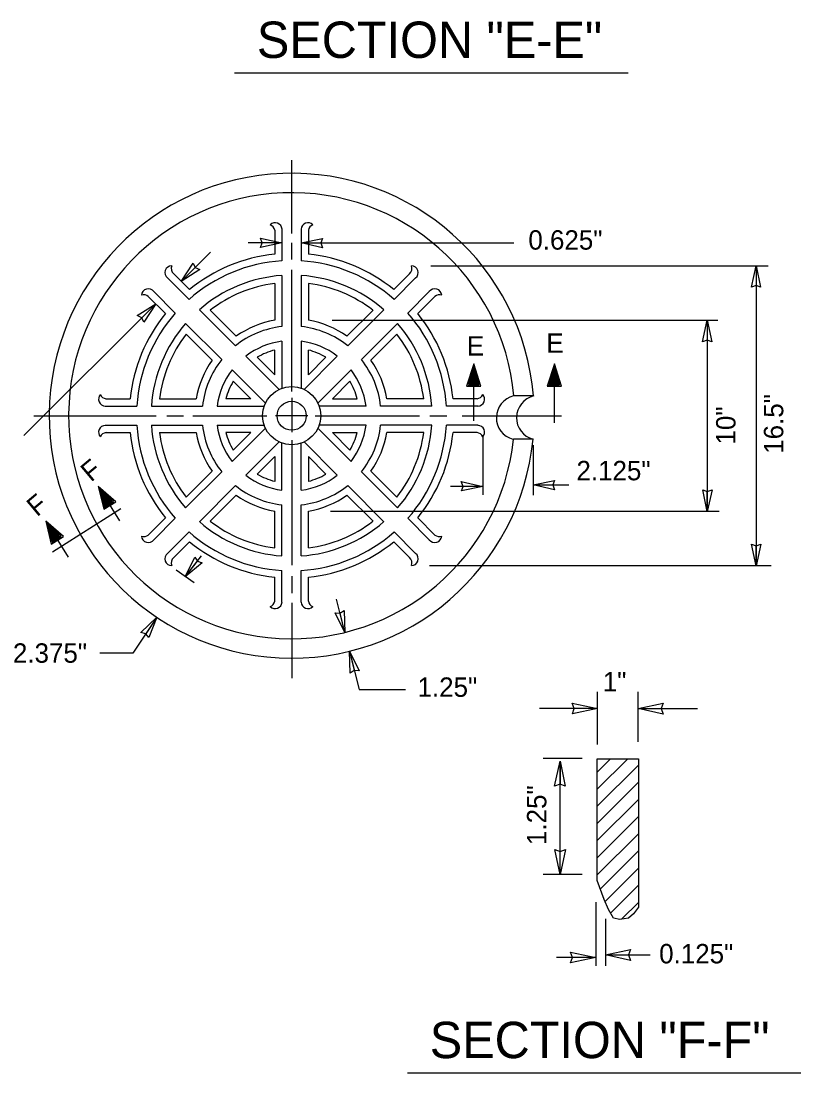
# Model space of a CAD drawing. Extents: x 19188 to 19495, y 20866 to 21061.
# Drawn here: x 19443.2 to 19476.89, y 20917.28 to 20962.72 of the extents above; entities that cross this region are included whole.
import ezdxf

# ---------------------------------------------------------------- set-up
doc = ezdxf.new("R2010")
doc.units = 0
doc.layers.add('G-ANNO-NOTE', color=7, linetype='Continuous')

msp = doc.modelspace()

# ---------------------------------------------------------------- linework, layer by layer
at = {"layer": 'G-ANNO-NOTE'}
for p, q in [((19452.424, 20960.486), (19469.42, 20960.486)), ((19454.471, 20953.729), (19454.471, 20952.36)), ((19455.299, 20953.729), (19455.299, 20952.36)), ((19454.157, 20953.681), (19454.157, 20952.649)), ((19455.613, 20953.681), (19455.613, 20952.649)), ((19454.471, 20953.135), (19453.007, 20953.135)), ((19454.471, 20953.135), (19453.618, 20953.135)), ((19455.299, 20953.135), (19464.487, 20953.135)), ((19455.299, 20953.135), (19456.152, 20953.135)), ((19450.122, 20951.476), (19451.382, 20952.736)), ((19450.122, 20951.476), (19450.725, 20952.079)), ((19460.905, 20952.151), (19475.47, 20952.151)), ((19474.952, 20952.151), (19474.952, 20939.195)), ((19474.952, 20952.151), (19474.952, 20951.298)), ((19450.456, 20950.697), (19449.529, 20951.624)), ((19449.797, 20951.8), (19450.474, 20951.124)), ((19454.471, 20951.731), (19454.471, 20949.523)), ((19455.299, 20951.731), (19455.299, 20949.523)), ((19459.973, 20951.8), (19459.296, 20951.124)), ((19459.314, 20950.697), (19460.241, 20951.624)), ((19448.937, 20951.031), (19449.863, 20950.105)), ((19454.157, 20951.384), (19454.157, 20949.795)), ((19455.613, 20951.384), (19455.613, 20949.795)), ((19460.833, 20951.031), (19459.907, 20950.105)), ((19448.696, 20950.828), (19449.437, 20950.087)), ((19461.074, 20950.828), (19460.333, 20950.087)), ((19449.015, 20950.508), (19443.319, 20944.812)), ((19449.015, 20950.508), (19448.412, 20949.905)), ((19450.901, 20950.252), (19452.462, 20948.691)), ((19451.368, 20950.229), (19452.492, 20949.105)), ((19458.402, 20950.229), (19457.278, 20949.105)), ((19458.869, 20950.252), (19457.308, 20948.691)), ((19450.308, 20949.66), (19451.869, 20948.098)), ((19456.633, 20949.795), (19473.295, 20949.795)), ((19459.461, 20949.66), (19457.9, 20948.098)), ((19472.843, 20949.795), (19472.843, 20941.539)), ((19472.843, 20949.795), (19472.843, 20948.942)), ((19450.331, 20949.192), (19451.455, 20948.069)), ((19459.438, 20949.192), (19458.315, 20948.069)), ((19454.471, 20948.89), (19454.471, 20946.858)), ((19455.299, 20948.89), (19455.299, 20946.858)), ((19454.157, 20947.44), (19454.157, 20948.51)), ((19455.613, 20947.44), (19455.613, 20948.51)), ((19452.909, 20948.243), (19454.347, 20946.806)), ((19454.157, 20947.44), (19453.401, 20948.197)), ((19456.86, 20948.243), (19455.424, 20946.806)), ((19455.613, 20947.44), (19456.37, 20948.197)), ((19462.76, 20945.446), (19462.76, 20947.908)), ((19466.238, 20945.363), (19466.238, 20947.908)), ((19452.317, 20947.651), (19453.757, 20946.211)), ((19457.453, 20947.651), (19456.013, 20946.211)), ((19453.12, 20946.404), (19452.364, 20947.16)), ((19456.65, 20946.404), (19457.407, 20947.16)), ((19462.507, 20946.979), (19462.971, 20946.979)), ((19465.984, 20946.979), (19466.449, 20946.979)), ((19465.328, 20946.527), (19464.487, 20946.527)), ((19446.829, 20946.089), (19448.2, 20946.089)), ((19446.869, 20946.404), (19447.911, 20946.404)), ((19448.83, 20946.089), (19451.037, 20946.089)), ((19449.176, 20946.404), (19450.765, 20946.404)), ((19451.67, 20946.089), (19453.701, 20946.089)), ((19453.12, 20946.404), (19452.05, 20946.404)), ((19454.89, 20946.441), (19454.89, 20944.959)), ((19458.1, 20946.089), (19456.069, 20946.089)), ((19456.65, 20946.404), (19457.719, 20946.404)), ((19460.94, 20946.089), (19458.733, 20946.089)), ((19460.594, 20946.404), (19459.005, 20946.404)), ((19462.941, 20946.089), (19461.57, 20946.089)), ((19462.901, 20946.404), (19461.859, 20946.404)), ((19455.586, 20945.671), (19454.191, 20945.671)), ((19446.829, 20945.258), (19448.2, 20945.258)), ((19448.83, 20945.258), (19451.037, 20945.258)), ((19451.67, 20945.258), (19453.701, 20945.258)), ((19452.317, 20943.696), (19453.757, 20945.137)), ((19457.453, 20943.696), (19456.013, 20945.137)), ((19458.1, 20945.258), (19456.069, 20945.258)), ((19460.94, 20945.258), (19458.733, 20945.258)), ((19462.941, 20945.258), (19461.57, 20945.258)), ((19446.869, 20944.944), (19447.911, 20944.944)), ((19449.176, 20944.944), (19450.765, 20944.944)), ((19453.12, 20944.944), (19452.05, 20944.944)), ((19453.12, 20944.944), (19452.364, 20944.187)), ((19456.65, 20944.944), (19457.407, 20944.187)), ((19456.65, 20944.944), (19457.719, 20944.944)), ((19460.594, 20944.944), (19459.005, 20944.944)), ((19462.901, 20944.944), (19461.859, 20944.944)), ((19463.143, 20944.759), (19463.143, 20942.26)), ((19465.314, 20944.656), (19464.472, 20944.656)), ((19452.909, 20943.104), (19454.347, 20944.541)), ((19454.471, 20942.457), (19454.471, 20944.49)), ((19455.299, 20942.457), (19455.299, 20944.49)), ((19456.86, 20943.104), (19455.424, 20944.541)), ((19465.317, 20944.407), (19465.317, 20942.245)), ((19454.157, 20943.907), (19453.401, 20943.151)), ((19454.157, 20943.907), (19454.157, 20942.837)), ((19455.613, 20943.907), (19456.37, 20943.151)), ((19455.613, 20943.907), (19455.613, 20942.837)), ((19450.331, 20942.155), (19451.455, 20943.279)), ((19459.438, 20942.155), (19458.315, 20943.279)), ((19450.308, 20941.688), (19451.869, 20943.249)), ((19459.461, 20941.688), (19457.9, 20943.249)), ((19446.534, 20942.62), (19447.452, 20941.13)), ((19450.901, 20941.095), (19452.462, 20942.656)), ((19458.869, 20941.095), (19457.308, 20942.656)), ((19463.143, 20942.62), (19461.746, 20942.62)), ((19463.143, 20942.62), (19462.291, 20942.62)), ((19465.317, 20942.68), (19466.86, 20942.68)), ((19465.317, 20942.68), (19466.17, 20942.68)), ((19472.843, 20941.539), (19472.843, 20942.392)), ((19446.806, 20941.696), (19447.201, 20941.94)), ((19451.368, 20941.118), (19452.492, 20942.242)), ((19458.402, 20941.118), (19457.278, 20942.242)), ((19444.552, 20939.787), (19447.505, 20941.659)), ((19454.157, 20939.963), (19454.157, 20941.552)), ((19454.471, 20939.617), (19454.471, 20941.824)), ((19455.299, 20939.617), (19455.299, 20941.824)), ((19455.613, 20939.963), (19455.613, 20941.552)), ((19456.568, 20941.552), (19473.36, 20941.552)), ((19444.268, 20941.118), (19445.229, 20939.558)), ((19448.696, 20940.52), (19449.437, 20941.261)), ((19448.937, 20940.316), (19449.863, 20941.243)), ((19460.833, 20940.316), (19459.907, 20941.243)), ((19461.074, 20940.52), (19460.333, 20941.261)), ((19450.456, 20940.65), (19449.529, 20939.723)), ((19459.314, 20940.65), (19460.241, 20939.723)), ((19444.54, 20940.194), (19444.935, 20940.437)), ((19449.797, 20939.546), (19450.474, 20940.224)), ((19459.973, 20939.546), (19459.296, 20940.224)), ((19474.952, 20939.195), (19474.952, 20940.049)), ((19450.289, 20938.715), (19451, 20939.616)), ((19450.289, 20938.715), (19450.817, 20939.384)), ((19460.84, 20939.196), (19475.599, 20939.196)), ((19449.9, 20939.015), (19450.677, 20938.475)), ((19454.471, 20937.618), (19454.471, 20938.987)), ((19455.299, 20937.618), (19455.299, 20938.987)), ((19454.157, 20937.666), (19454.157, 20938.698)), ((19455.613, 20937.666), (19455.613, 20938.698)), ((19457.179, 20936.311), (19456.827, 20937.754)), ((19449.065, 20936.967), (19448.023, 20935.411)), ((19449.065, 20936.967), (19448.59, 20936.258)), ((19457.179, 20936.311), (19456.977, 20937.14)), ((19448.023, 20935.411), (19446.599, 20935.411)), ((19457.391, 20935.501), (19457.798, 20933.848)), ((19457.391, 20935.501), (19457.595, 20934.673)), ((19457.798, 20933.848), (19459.804, 20933.848)), ((19468.093, 20931.47), (19468.093, 20933.742)), ((19469.853, 20931.59), (19469.853, 20933.742)), ((19468.093, 20933.025), (19465.6, 20933.025)), ((19468.093, 20933.025), (19467.098, 20933.025)), ((19469.853, 20933.025), (19472.42, 20933.025)), ((19469.853, 20933.025), (19470.848, 20933.025)), ((19467.433, 20930.873), (19465.747, 20930.873)), ((19466.48, 20925.852), (19466.48, 20930.753)), ((19466.48, 20930.753), (19466.48, 20929.759)), ((19468.091, 20930.857), (19469.869, 20930.857)), ((19468.091, 20925.598), (19468.091, 20930.857)), ((19468.091, 20929.541), (19469.408, 20930.857)), ((19468.091, 20930.281), (19468.667, 20930.857)), ((19468.091, 20928.8), (19469.869, 20930.578)), ((19469.869, 20930.857), (19469.869, 20924.445)), ((19468.091, 20928.059), (19469.869, 20929.837)), ((19468.091, 20927.319), (19469.869, 20929.097)), ((19468.091, 20926.578), (19469.869, 20928.356)), ((19468.091, 20925.838), (19469.869, 20927.616)), ((19466.48, 20925.852), (19466.48, 20926.847)), ((19468.227, 20925.233), (19469.869, 20926.875)), ((19468.429, 20924.694), (19469.869, 20926.134)), ((19467.433, 20925.852), (19465.747, 20925.852)), ((19468.65, 20924.175), (19469.869, 20925.394)), ((19468.02, 20924.656), (19468.02, 20921.906)), ((19469.154, 20923.939), (19469.869, 20924.653)), ((19468.439, 20923.939), (19468.439, 20921.906)), ((19468.439, 20922.384), (19470.367, 20922.384)), ((19468.439, 20922.384), (19469.434, 20922.384)), ((19468.02, 20922.265), (19466.333, 20922.265)), ((19468.02, 20922.265), (19467.025, 20922.265)), ((19459.891, 20917.283), (19476.888, 20917.283))]:
    msp.add_line(p, q, dxfattribs=at)
for points in [[(19454.89, 20953.545), (19454.89, 20956.708)], [(19453.618, 20953.135), (19453.543, 20953.339), (19454.471, 20953.135), (19453.545, 20952.94), (19453.618, 20953.135)], [(19456.152, 20953.135), (19456.227, 20952.931), (19455.299, 20953.135), (19456.225, 20953.33), (19456.152, 20953.135)], [(19454.89, 20952.421), (19454.89, 20953.146)], [(19450.725, 20952.079), (19450.922, 20951.987), (19450.122, 20951.476), (19450.639, 20952.268), (19450.725, 20952.079)], [(19454.89, 20946.717), (19454.89, 20951.968)], [(19474.952, 20951.298), (19474.748, 20951.224), (19474.952, 20952.151), (19475.147, 20951.225), (19474.952, 20951.298)], [(19448.412, 20949.905), (19448.215, 20949.996), (19449.015, 20950.508), (19448.498, 20949.716), (19448.412, 20949.905)], [(19472.843, 20948.942), (19472.639, 20948.868), (19472.843, 20949.795), (19473.037, 20948.87), (19472.843, 20948.942)], [(19462.444, 20946.943), (19463.065, 20946.943), (19462.76, 20947.908), (19462.444, 20946.943)], [(19465.921, 20946.943), (19466.542, 20946.943), (19466.238, 20947.908), (19465.921, 20946.943)], [(19462.524, 20947.021), (19462.989, 20947.021), (19462.761, 20947.744), (19462.524, 20947.021)], [(19462.581, 20947.06), (19462.93, 20947.06), (19462.759, 20947.602), (19462.581, 20947.06)], [(19462.63, 20947.096), (19462.892, 20947.096), (19462.763, 20947.502), (19462.63, 20947.096)], [(19462.675, 20947.124), (19462.852, 20947.124), (19462.766, 20947.399), (19462.675, 20947.124)], [(19466.001, 20947.021), (19466.467, 20947.021), (19466.239, 20947.744), (19466.001, 20947.021)], [(19466.058, 20947.06), (19466.408, 20947.06), (19466.237, 20947.602), (19466.058, 20947.06)], [(19466.107, 20947.096), (19466.369, 20947.096), (19466.241, 20947.502), (19466.107, 20947.096)], [(19466.153, 20947.124), (19466.33, 20947.124), (19466.243, 20947.399), (19466.153, 20947.124)], [(19462.719, 20947.153), (19462.817, 20947.153), (19462.769, 20947.306), (19462.719, 20947.153)], [(19466.197, 20947.153), (19466.295, 20947.153), (19466.246, 20947.306), (19466.197, 20947.153)], [(19443.747, 20945.671), (19449.037, 20945.671)], [(19449.493, 20945.671), (19450.223, 20945.671)], [(19450.625, 20945.671), (19453.811, 20945.671)], [(19455.904, 20945.671), (19460.408, 20945.671)], [(19460.862, 20945.671), (19461.597, 20945.671)], [(19462.249, 20945.671), (19466.545, 20945.671)], [(19454.89, 20944.614), (19454.89, 20939.213)], [(19462.29, 20942.62), (19462.215, 20942.824), (19463.143, 20942.62), (19462.218, 20942.426), (19462.29, 20942.62)], [(19466.17, 20942.681), (19466.245, 20942.477), (19465.317, 20942.68), (19466.243, 20942.875), (19466.17, 20942.681)], [(19446.77, 20941.633), (19447.299, 20941.958), (19446.534, 20942.62), (19446.77, 20941.633)], [(19446.797, 20941.741), (19447.194, 20941.985), (19446.621, 20942.481), (19446.797, 20941.741)], [(19472.842, 20942.392), (19473.046, 20942.467), (19472.843, 20941.539), (19472.648, 20942.465), (19472.842, 20942.392)], [(19446.825, 20941.805), (19447.123, 20941.987), (19446.693, 20942.36), (19446.825, 20941.805)], [(19446.849, 20941.86), (19447.072, 20941.998), (19446.749, 20942.277), (19446.849, 20941.86)], [(19446.872, 20941.909), (19447.023, 20942.002), (19446.806, 20942.19), (19446.872, 20941.909)], [(19446.894, 20941.956), (19446.978, 20942.008), (19446.857, 20942.112), (19446.894, 20941.956)], [(19444.504, 20940.131), (19445.033, 20940.456), (19444.268, 20941.118), (19444.504, 20940.131)], [(19444.532, 20940.239), (19444.929, 20940.483), (19444.355, 20940.979), (19444.532, 20940.239)], [(19444.56, 20940.302), (19444.857, 20940.485), (19444.427, 20940.858), (19444.56, 20940.302)], [(19444.583, 20940.358), (19444.806, 20940.496), (19444.484, 20940.775), (19444.583, 20940.358)], [(19444.607, 20940.407), (19444.757, 20940.5), (19444.539, 20940.688), (19444.607, 20940.407)], [(19444.628, 20940.454), (19444.712, 20940.505), (19444.591, 20940.61), (19444.628, 20940.454)], [(19474.951, 20940.049), (19475.156, 20940.123), (19474.952, 20939.195), (19474.757, 20940.122), (19474.951, 20940.049)], [(19450.817, 20939.384), (19451.024, 20939.317), (19450.289, 20938.715), (19450.71, 20939.562), (19450.817, 20939.384)], [(19454.89, 20938.748), (19454.89, 20938.002)], [(19454.89, 20937.592), (19454.89, 20934.339)], [(19448.59, 20936.258), (19448.379, 20936.309), (19449.065, 20936.967), (19448.712, 20936.089), (19448.59, 20936.258)], [(19456.976, 20937.14), (19457.157, 20937.26), (19457.179, 20936.311), (19456.77, 20937.164), (19456.976, 20937.14)], [(19457.595, 20934.673), (19457.415, 20934.551), (19457.391, 20935.501), (19457.801, 20934.648), (19457.595, 20934.673)], [(19467.098, 20933.025), (19467.011, 20933.262), (19468.093, 20933.025), (19467.013, 20932.798), (19467.098, 20933.025)], [(19470.849, 20933.025), (19470.935, 20932.787), (19469.853, 20933.025), (19470.933, 20933.252), (19470.849, 20933.025)], [(19466.48, 20929.758), (19466.242, 20929.671), (19466.48, 20930.753), (19466.707, 20929.673), (19466.48, 20929.758)], [(19466.48, 20926.847), (19466.718, 20926.934), (19466.48, 20925.852), (19466.253, 20926.932), (19466.48, 20926.847)], [(19469.869, 20924.445), (19469.658, 20924.159), (19469.432, 20923.975), (19469.057, 20923.913), (19468.794, 20923.975), (19468.568, 20924.342), (19468.38, 20924.771), (19468.091, 20925.598)], [(19467.025, 20922.265), (19466.938, 20922.503), (19468.02, 20922.265), (19466.94, 20922.038), (19467.025, 20922.265)], [(19469.434, 20922.385), (19469.521, 20922.147), (19468.439, 20922.384), (19469.519, 20922.612), (19469.434, 20922.385)]]:
    msp.add_lwpolyline(points, dxfattribs=at)
for radius in [1.257, 0.628]:
    msp.add_circle((19454.89, 20945.671), radius, dxfattribs=at)
for centre, radius, start, end in [((19454.89, 20945.671), 10.473, 4.6895, 354.442), ((19454.89, 20945.671), 9.635, 5.0984, 353.957), ((19454.176, 20953.711), 0.296, 3.5498, 135.4888), ((19453.864, 20953.641), 0.296, 7.8293, 69.9472), ((19455.594, 20953.711), 0.296, 44.5112, 176.4502), ((19455.906, 20953.641), 0.296, 110.0528, 172.1707), ((19454.89, 20945.671), 7.017, 95.9971, 129.003), ((19454.88, 20945.671), 7.017, 50.997, 84.0029), ((19449.712, 20951.856), 0.296, 90.8671, 231.6571), ((19449.979, 20952.033), 0.296, 156.4305, 231.8202), ((19454.89, 20945.671), 6.703, 93.5833, 131.4166), ((19454.88, 20945.671), 6.703, 48.5834, 86.4167), ((19459.791, 20952.033), 0.296, 308.1798, 23.5695), ((19460.058, 20951.856), 0.296, 308.3429, 89.1329), ((19454.89, 20945.671), 6.074, 93.9546, 131.0453), ((19454.88, 20945.671), 6.074, 48.9547, 86.0454), ((19448.697, 20950.858), 0.296, 35.8606, 176.6506), ((19454.89, 20945.671), 5.76, 97.312, 127.6881), ((19454.88, 20945.671), 5.76, 52.3119, 82.688), ((19461.073, 20950.858), 0.296, 3.3494, 144.1394), ((19448.508, 20950.599), 0.296, 50.5694, 111.0872), ((19461.262, 20950.599), 0.296, 68.9128, 129.4306), ((19454.89, 20945.671), 6.703, 138.5834, 176.4167), ((19454.88, 20945.671), 6.703, 3.5833, 41.4166), ((19454.89, 20945.671), 7.017, 140.997, 174.0029), ((19454.89, 20945.671), 6.074, 138.9547, 176.0454), ((19454.89, 20945.671), 4.189, 100.0787, 124.9215), ((19454.88, 20945.671), 4.189, 55.0785, 79.9213), ((19454.88, 20945.671), 6.074, 3.9546, 41.0453), ((19454.88, 20945.671), 7.017, 5.9971, 39.003), ((19454.89, 20945.671), 5.76, 142.3119, 172.688), ((19454.89, 20945.671), 3.875, 96.2063, 128.7936), ((19454.88, 20945.671), 3.875, 51.2064, 83.7937), ((19454.88, 20945.671), 5.76, 7.312, 37.6881), ((19454.89, 20945.671), 3.247, 97.4137, 127.5861), ((19454.88, 20945.671), 3.247, 52.4139, 82.5863), ((19454.89, 20945.671), 2.932, 104.4775, 120.5227), ((19454.88, 20945.671), 2.932, 59.4773, 75.5225), ((19454.89, 20945.671), 4.189, 145.0785, 169.9213), ((19454.89, 20945.671), 3.875, 141.2064, 173.7937), ((19454.88, 20945.671), 3.875, 6.2063, 38.7936), ((19454.88, 20945.671), 4.189, 10.0787, 34.9215), ((19454.89, 20945.671), 3.247, 142.4139, 172.5863), ((19454.88, 20945.671), 3.247, 7.4137, 37.5861), ((19454.89, 20945.671), 2.932, 149.4773, 165.5225), ((19454.88, 20945.671), 2.932, 14.4775, 30.5227), ((19446.844, 20946.387), 0.296, 137.1278, 269.0668), ((19446.899, 20946.702), 0.296, 202.6694, 264.7873), ((19462.871, 20946.702), 0.296, 275.2126, 337.3306), ((19462.927, 20946.387), 0.296, 270.9332, 42.8722), ((19464.694, 20945.588), 0.964, 103.2056, 255.227), ((19465.563, 20945.588), 0.964, 103.2056, 255.227), ((19446.844, 20944.96), 0.296, 90.9332, 222.8722), ((19454.89, 20945.677), 6.703, 183.5833, 221.4166), ((19454.89, 20945.677), 6.074, 183.9546, 221.0453), ((19454.89, 20945.677), 3.875, 186.2063, 218.7936), ((19454.89, 20945.677), 3.247, 187.4137, 217.5861), ((19454.88, 20945.677), 3.247, 322.4139, 352.5863), ((19454.88, 20945.677), 3.875, 321.2064, 353.7937), ((19454.88, 20945.677), 6.074, 318.9547, 356.0454), ((19454.88, 20945.677), 6.703, 318.5834, 356.4167), ((19462.927, 20944.96), 0.296, 317.1278, 89.0668), ((19446.899, 20944.646), 0.296, 95.2127, 157.3306), ((19454.89, 20945.677), 7.017, 185.9971, 219.003), ((19454.89, 20945.677), 5.76, 187.312, 217.6881), ((19454.89, 20945.677), 4.189, 190.0787, 214.9215), ((19454.89, 20945.677), 2.932, 194.4775, 210.5227), ((19454.88, 20945.677), 2.932, 329.4773, 345.5225), ((19454.88, 20945.677), 4.189, 325.0785, 349.9213), ((19454.88, 20945.677), 5.76, 322.3119, 352.688), ((19454.88, 20945.677), 7.017, 320.997, 354.0029), ((19462.871, 20944.646), 0.296, 22.6694, 84.7873), ((19454.89, 20945.677), 3.247, 232.4139, 262.5863), ((19454.89, 20945.677), 2.932, 239.4773, 255.5225), ((19454.88, 20945.677), 3.247, 277.4137, 307.5861), ((19454.88, 20945.677), 2.932, 284.4775, 300.5227), ((19454.89, 20945.677), 3.875, 231.2064, 263.7937), ((19454.88, 20945.677), 3.875, 276.2063, 308.7936), ((19454.89, 20945.677), 4.189, 235.0785, 259.9213), ((19454.88, 20945.677), 4.189, 280.0787, 304.9215), ((19454.89, 20945.677), 6.074, 228.9547, 266.0454), ((19454.89, 20945.677), 5.76, 232.3119, 262.688), ((19454.88, 20945.677), 6.074, 273.9546, 311.0453), ((19454.88, 20945.677), 5.76, 277.312, 307.6881), ((19454.89, 20945.677), 6.703, 228.5834, 266.4167), ((19454.88, 20945.677), 6.703, 273.5833, 311.4166), ((19448.508, 20940.748), 0.296, 248.9128, 309.4306), ((19448.697, 20940.489), 0.296, 183.3494, 324.1394), ((19454.89, 20945.677), 7.017, 230.997, 264.0029), ((19454.88, 20945.677), 7.017, 275.9971, 309.003), ((19461.073, 20940.489), 0.296, 215.8606, 356.6506), ((19461.262, 20940.748), 0.296, 230.5694, 291.0872), ((19449.712, 20939.492), 0.296, 128.3429, 269.1329), ((19460.058, 20939.492), 0.296, 270.8671, 51.6571), ((19449.979, 20939.314), 0.296, 128.1798, 203.5695), ((19459.791, 20939.314), 0.296, 336.4305, 51.8202), ((19453.864, 20937.707), 0.296, 290.0528, 352.1707), ((19454.176, 20937.637), 0.296, 224.5112, 356.4502), ((19455.594, 20937.637), 0.296, 183.5498, 315.4888), ((19455.906, 20937.707), 0.296, 187.8293, 249.9472)]:
    msp.add_arc(centre, radius, start, end, dxfattribs=at)

# ---------------------------------------------------------------- texts
for s, height, p in [('SECTION "E-E"', 1.57098, (19453.386, 20961.126)), ('0.625"', 0.8379, (19465.112, 20952.846)), ('E', 0.838, (19465.889, 20948.39)), ('E', 0.838, (19462.458, 20948.27)), ('2.125"', 0.8379, (19467.189, 20942.883)), ('2.375"', 0.8379, (19442.849, 20935.002)), ('1.25"', 0.8379, (19460.326, 20933.53)), ('1"', 0.8379, (19468.327, 20933.765)), ('0.125"', 0.8379, (19470.763, 20922.017)), ('SECTION "F-F"', 1.57098, (19460.853, 20917.923))]:
    msp.add_text(s, height=height, dxfattribs=at).set_placement(p)
for s, height, rotation, p in [('16.5"', 0.8379, 90, (19476.124, 20944.027)), ('10"', 0.8379, 90, (19474.06, 20944.428)), ('F', 0.838, 40, (19446.221, 20942.78)), ('F', 0.838, 40, (19443.89, 20941.278)), ('1.25"', 0.8379, 90, (19465.89, 20927.13))]:
    msp.add_text(s, height=height, rotation=rotation, dxfattribs=at).set_placement(p)

doc.saveas('drawing.dxf')
